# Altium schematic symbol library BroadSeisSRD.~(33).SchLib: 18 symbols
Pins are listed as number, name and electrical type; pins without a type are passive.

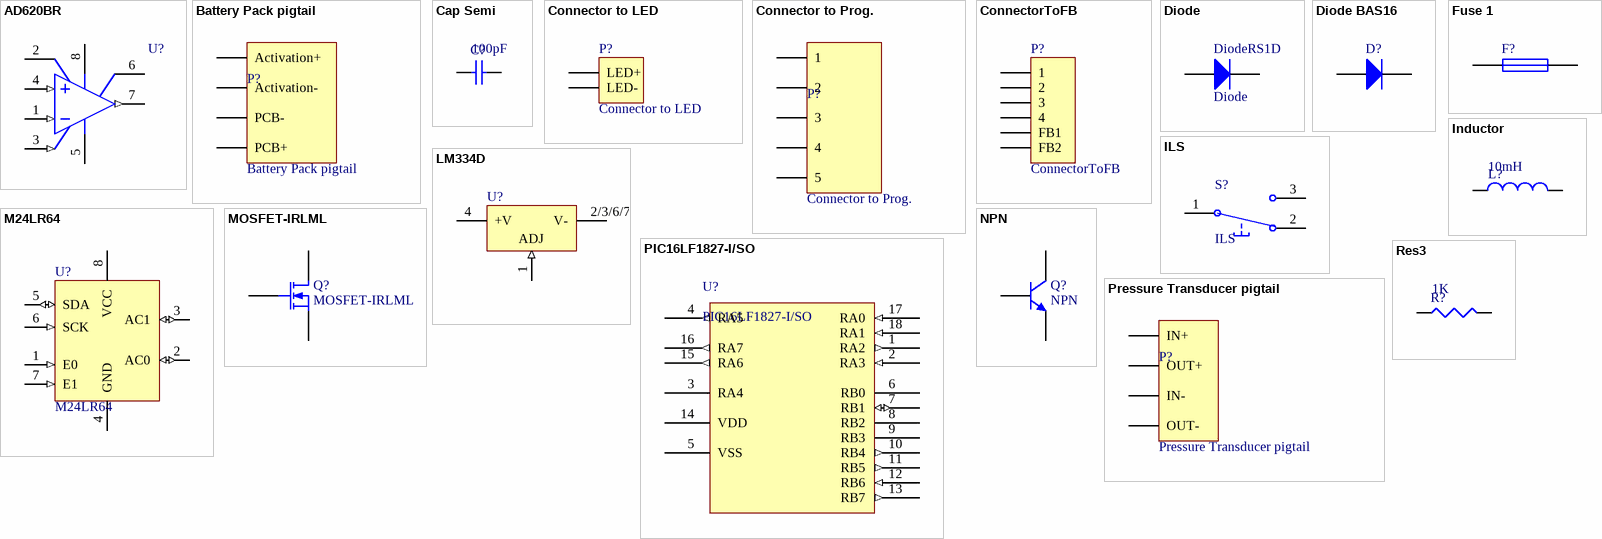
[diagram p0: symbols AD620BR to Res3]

## AD620BR
designator U?
Low-Cost, Low-Power Instrumentation Amplifier
footprint R-8D_N (SOIC, 8-Leads, Body 4.9x3.9mm, Pitch 1.27mm, IPC Medium Density)
footprint R-8D_L (SOIC, 8-Leads, Body 4.9x3.9mm, Pitch 1.27mm, IPC High Density)
footprint R-8D_M (SOIC, 8-Leads, Body 4.9x3.9mm, Pitch 1.27mm, IPC Low Density)
3D model R-8D (8-Pin Narrow Body Small Outline Integrated Circuit 1.27 mm Pitch)
simulation model AD620B (SUBCKT)
pins: 1 -IN (in), 2 RG, 3 REF (in), 4 +IN (in), 5 V- (power), 6 RG, 7 OUT (out), 8 V+ (power)

## Battery Pack pigtail
designator P?
Header, 4-Pin
footprint HDR1X4 (Connector; Header; 4 Position)
signal-integrity model Connector
pins: 1 Activation+, 2 Activation-, 3 PCB-, 4 PCB+

## Cap Semi
designator C?  value 100pF
Capacitor (Semiconductor SIM Model)
simulation model CAP (Semiconductor Capacitor)
signal-integrity model Cap Semi
footprint 1608[0603] (Chip Capacitor, Body 1.6x0.8mm, IPC High Density)
pins: 1, 2

## Connector to LED
designator P?
Header, 2-Pin
footprint HDR1X2 (Connector; Header; 2 Position)
signal-integrity model Connector
pins: 1 LED+, 2 LED-

## Connector to Prog.
designator P?
Header, 5-Pin
footprint HDR1X5 (Connector; Header; 5 Position)
signal-integrity model Connector
pins: 1, 2, 3, 4, 5

## ConnectorToFB
designator P?
Header, 6-Pin
signal-integrity model Connector
footprint HIROSE DF3A-6P (Connector; Header; 6 Position)
pins: 1, 2, 3, 4, 5 FB2, 6 FB1

## Diode
designator DiodeRS1D
Default Diode
simulation model DIODE (Diode)
signal-integrity model Diode
footprint DiodeRS1D(recommendedfootprint) (DO-214-AB/SMC; 2 C-Bend Leads; Body 7.9 x 5.9 mm, inc. leads (LxW))
pins: 1 A, 2 K

## Diode BAS16
designator D?
Silicon Switching Diode for High-Speed Switching; Note: Pin 2 is not connected and not drawn.
simulation model BAS16 (SUBCKT)
footprint SOT23_M (SOT23, 3-Leads, Body 2.9x1.3mm, Pitch 0.95mm, Lead Span 2.3mm - Reverse Pinning, IPC Low Density)
pins: 1 A, 3 K

## Fuse 1
designator F?
Fuse
simulation model FUSE (Spice Subcircuit)
footprint FU(recommendedfootprint) (Thru-Hole; 2 Leads)
pins: 1, 2

## ILS
designator S?
SPDT Subminiature Toggle Switch, Right Angle Mounting, Vertical Actuation
footprint ILS
pins: 1, 2, 3

## Inductor
designator L?  value 10mH
Inductor; Code_IEC: 1005
simulation model INDUCTOR (Inductor)
signal-integrity model Inductor
footprint INDC4532 (Chip Inductor, Body 4.5x3.2mm, IPC High Density)
pins: 1, 2

## LM334D
designator U?
Three Terminal Adjustable Current Source
footprint SO8_L (SOIC, 8-Leads, Body 4.9x3.9mm, Pitch 1.27mm, IPC High Density)
footprint SO8_M (SOIC, 8-Leads, Body 4.9x3.9mm, Pitch 1.27mm, IPC Low Density)
3D model SO8 (8-Pin Small Outline Integrated Circuit 1.27 mm Pitch)
footprint SO8_N (SOIC, 8-Leads, Body 4.9x3.9mm, Pitch 1.27mm, IPC Medium Density)
pins: 1 ADJ (in), 2/3/6/7 V- (power), 4 +V (power)

## M24LR64
designator U?
32 Kbit Serial I²C Bus EEPROM
3D model SO8W (8-Pin Small Outline Package 1.27 mm Pitch)
footprint SO8N_N (SOP, 8-Leads, Body 5.3x5.3mm, Pitch 1.27mm, IPC Medium Density)
pins: 1 E0 (in), 2 AC0 (io), 3 AC1 (io), 4 GND (power), 5 SDA (io), 6 SCK (in), 7 E1 (in), 8 VCC (power)

## MOSFET-IRLML
designator Q?
N-Channel MOSFET
simulation model NMOS (MOSFET-N)
footprint transistor_SOT-23(recommendedfootprint) (SOT23, 3-Leads, Body 2.9x1.3mm, Pitch 0.95mm, Lead Span 2.5mm, IPC Low Density)
pins: 1 D, 2 G, 3 S

## NPN
designator Q?
NPN Bipolar Transistor
simulation model NPN
signal-integrity model NPN
footprint transistor_SOT-23(recommendedfootprint) (SOT23, 3-Leads, Body 2.9x1.3mm, Pitch 0.95mm, Lead Span 2.5mm, IPC Low Density)
pins: 1 C, 2 B, 3 E

## PIC16LF1827-I/SO
designator U?
EPROM-Based 8-Bit CMOS Microcontroller, 25 Bytes RAM, 4 MHz, 18-Pin SOIC, 3.0 to 5.5V Supply Range, Extended Temperature; Note: Verify oscillator characteristics if changing from this device to another.; Note: 20mA source and 25mA sink per I/O.
footprint SOIC-SO18_N (SOIC, 18-Leads, Body 11.5x7.5mm, Pitch 1.27mm, IPC Medium Density)
footprint SOIC-SO18_L (SOIC, 18-Leads, Body 11.5x7.5mm, Pitch 1.27mm, IPC High Density)
footprint SOIC-SO18_M (SOIC, 18-Leads, Body 11.5x7.5mm, Pitch 1.27mm, IPC Low Density)
pins: 1 RA2 (out), 2 RA3 (in), 3 RA4 (power), 4 RA5 (out), 5 VSS (power), 6 RB0 (power), 7 RB1 (io), 8 RB2 (power), 9 RB3 (power), 10 RB4 (out), 11 RB5 (out), 12 RB6 (in), 13 RB7 (out), 14 VDD (power), 15 RA6 (out), 16 RA7 (out), 17 RA0 (in), 18 RA1 (in)

## Pressure Transducer pigtail
designator P?
Header, 4-Pin
footprint HDR1X4 (Connector; Header; 4 Position)
signal-integrity model Connector
pins: 1 IN+, 2 OUT+, 3 IN-, 4 OUT-

## Res3
designator R?  value 1K
Resistor
simulation model RESISTOR (Resistor)
signal-integrity model Res
footprint J1-0603 (Chip Capacitor, Body 1.6x0.8mm, IPC High Density)
pins: 1, 2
